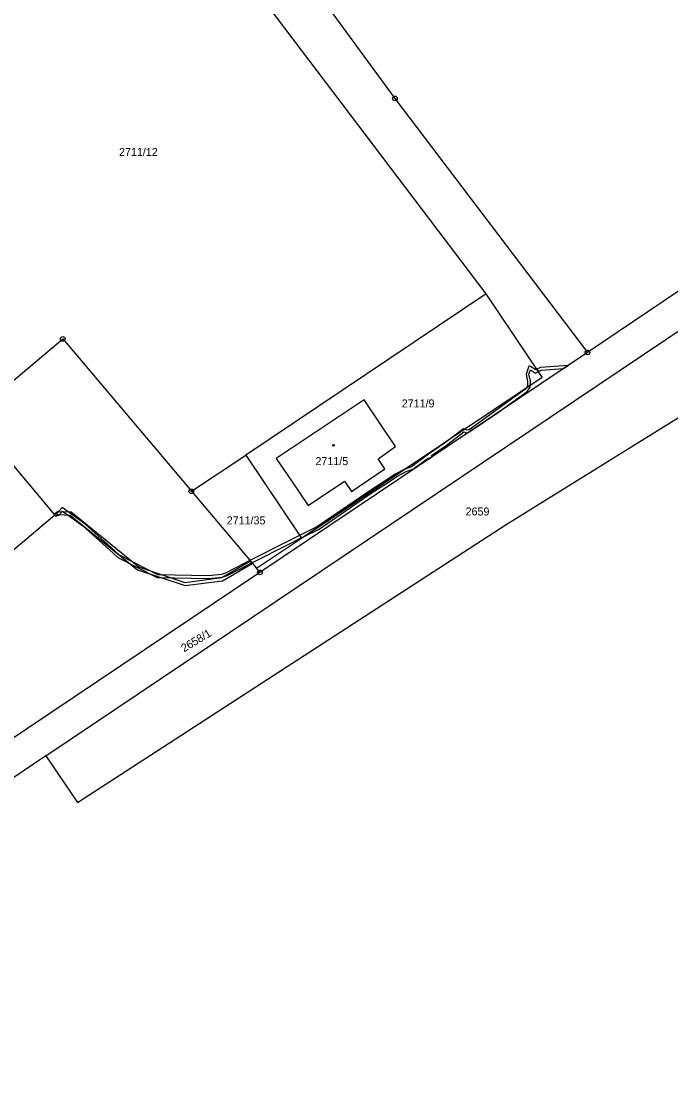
# Model space of a CAD drawing. Extents: x -562167 to -556918, y -1077891 to -1070763.
# Drawn here: x -561195.6 to -561057.6, y -1075746.5 to -1075522.2 of the extents above; entities that cross this region are included whole.
import ezdxf

# ---------------------------------------------------------------- set-up
doc = ezdxf.new("R2010")
doc.units = 0
for name, color, linetype in [('Hranice parcel', 7, 'Continuous'), ('Parcelní čísla', 7, 'Continuous'), ('Věcná břemena k části', 7, 'Continuous'), ('Značky bodu BP', 7, 'Continuous'), ('Značky budov', 7, 'Continuous')]:
    doc.layers.add(name, color=color, linetype=linetype)

msp = doc.modelspace()

# ---------------------------------------------------------------- linework, layer by layer
at = {"layer": 'Hranice parcel'}
for p, q in [((-561052.89, -1075577.55), (-561075.29, -1075592.6)), ((-561096.76, -1075580.15), (-561147.86, -1075614.39)), ((-561075.29, -1075592.6), (-561144.84, -1075639.34)), ((-561122.73, -1075602.7), (-561141.37, -1075615.12)), ((-561159.41, -1075622.1), (-561147.86, -1075614.39)), ((-561147.86, -1075614.39), (-561136.01, -1075632.09)), ((-561159.41, -1075622.1), (-561145.59, -1075638.46)), ((-561145.59, -1075638.46), (-561136.01, -1075632.09)), ((-561144.84, -1075639.34), (-561145.59, -1075638.46)), ((-561190.29, -1075678.29), (-561291.97, -1075746.53))]:
    msp.add_line(p, q, dxfattribs=at)
for points in [[(-561192.98, -1075442.18), (-561152.03, -1075491.45), (-561130.12, -1075519.56), (-561116.17, -1075538.61), (-561075.29, -1075592.6)], [(-561096.76, -1075580.15), (-561166.81, -1075487.64), (-561244.99, -1075544.16)], [(-561190.29, -1075678.29), (-561048.71, -1075583.16), (-561017.82, -1075561.43)], [(-561190.29, -1075678.29), (-561183.6, -1075688.25), (-561092.57, -1075629.13), (-561039.17, -1075596), (-561011.55, -1075569.85)], [(-561136.01, -1075632.09), (-561084.9, -1075597.84), (-561096.76, -1075580.15)], [(-561200.81, -1075601.59), (-561195.77, -1075597.33), (-561186.73, -1075589.72), (-561159.41, -1075622.1)], [(-561141.37, -1075615.12), (-561138.14, -1075619.9), (-561134.58, -1075625.14), (-561126.9, -1075619.93), (-561125.39, -1075622.11), (-561118.3, -1075617.3), (-561119.7, -1075615.23), (-561116.05, -1075612.57), (-561122.73, -1075602.7)], [(-561197.14, -1075616.68), (-561244.7, -1075656.87), (-561235.97, -1075667.26), (-561188.38, -1075627.09), (-561197.14, -1075616.68)], [(-561144.84, -1075639.34), (-561194.19, -1075672.48), (-561227.05, -1075694.53)]]:
    msp.add_lwpolyline(points, dxfattribs=at)
at = {"layer": 'Věcná břemena k části'}
for points in [[(-561087.99, -1075598.77), (-561088.02, -1075599.75), (-561088.27, -1075600.1), (-561087.41, -1075599.52), (-561087.39, -1075598.71), (-561087.7, -1075597.23), (-561087.38, -1075596.29), (-561086.3, -1075596.97), (-561085.69, -1075596.67), (-561086.02, -1075596.17), (-561086.26, -1075596.29), (-561087.18, -1075595.7), (-561087.5, -1075595.5), (-561087.78, -1075595.6), (-561087.9, -1075595.96), (-561088.32, -1075597.19)], [(-561085.28, -1075595.8), (-561086.02, -1075596.17), (-561085.69, -1075596.67), (-561085.12, -1075596.38), (-561080.41, -1075596.04), (-561079.4, -1075595.36)], [(-561088.55, -1075600.49), (-561100.43, -1075609.07), (-561100.9, -1075609.1), (-561101.41, -1075608.9), (-561103.95, -1075610.6), (-561105.63, -1075611.9), (-561109.07, -1075614.23), (-561112.68, -1075616.89), (-561113.99, -1075617.37), (-561114.23, -1075617.5), (-561135.33, -1075631.63), (-561132.28, -1075630.12), (-561120.97, -1075622.35), (-561117.74, -1075620.33), (-561115.79, -1075618.95), (-561113.75, -1075617.93), (-561112.4, -1075617.43), (-561109.06, -1075614.97), (-561108.9, -1075615.19), (-561108.24, -1075614.74), (-561108.4, -1075614.51), (-561105.27, -1075612.38), (-561101.53, -1075609.5), (-561101, -1075609.7), (-561100.72, -1075609.69), (-561094.14, -1075605.27), (-561088.11, -1075600.91), (-561087.42, -1075599.95), (-561087.41, -1075599.52), (-561088.27, -1075600.1)], [(-561103.95, -1075610.6), (-561101.41, -1075608.9), (-561101.63, -1075608.82)], [(-561136.07, -1075632), (-561135.33, -1075631.63), (-561114.23, -1075617.5), (-561116.09, -1075618.43), (-561118.08, -1075619.83), (-561121.29, -1075621.85), (-561132.58, -1075629.6), (-561136.41, -1075631.5), (-561139.11, -1075632.84), (-561146.96, -1075636.84), (-561146.56, -1075637.31), (-561138.85, -1075633.38)], [(-561176.87, -1075634.47), (-561175.02, -1075636.14), (-561166.7, -1075640.45), (-561155.71, -1075640.65), (-561152.9, -1075640.38), (-561151.93, -1075640.05), (-561146.56, -1075637.31), (-561146.96, -1075636.84), (-561152.17, -1075639.49), (-561153.02, -1075639.78), (-561155.73, -1075640.05), (-561166.54, -1075639.85), (-561174.68, -1075635.64), (-561176.47, -1075634.03), (-561182.05, -1075628.98), (-561186.85, -1075625.54), (-561188.04, -1075626.87), (-561187.6, -1075627.27), (-561186.77, -1075626.34), (-561182.43, -1075629.44)], [(-561170.86, -1075638.77), (-561160.75, -1075642.13), (-561152.81, -1075641.1), (-561146.48, -1075637.41), (-561146.87, -1075636.94), (-561153.01, -1075640.52), (-561160.69, -1075641.52), (-561170.56, -1075638.23), (-561184.93, -1075626.57), (-561187.87, -1075626.46), (-561188.48, -1075626.97), (-561188.38, -1075627.09), (-561188.09, -1075627.43), (-561187.66, -1075627.06), (-561185.16, -1075627.17)]]:
    msp.add_lwpolyline(points, close=True, dxfattribs=at)
at = {"layer": 'Značky bodu BP'}
for centre, radius in [((-561116.17, -1075538.61), 0.5), ((-561116.17, -1075538.61), 0.0303), ((-561186.73, -1075589.72), 0.5), ((-561186.73, -1075589.72), 0.0303), ((-561075.29, -1075592.6), 0.5), ((-561075.29, -1075592.6), 0.0303), ((-561159.41, -1075622.1), 0.5), ((-561159.41, -1075622.1), 0.0303), ((-561144.84, -1075639.34), 0.5), ((-561144.84, -1075639.34), 0.0303)]:
    msp.add_circle(centre, radius, dxfattribs=at)
at = {"layer": 'Značky budov'}
msp.add_circle((-561129.22, -1075612.33), 0.175, dxfattribs=at)

# ---------------------------------------------------------------- texts
at = {"layer": 'Parcelní čísla'}
for s, p in [('2711/12', (-561174.77, -1075550.85)), ('2711/9', (-561114.72, -1075604.28)), ('2711/5', (-561133.05, -1075616.54)), ('2659', (-561101.16, -1075627.24)), ('2711/35', (-561151.89, -1075629.13))]:
    msp.add_text(s, height=1.7, dxfattribs=at).set_placement(p)
msp.add_text('2658/1', height=1.7, rotation=31, dxfattribs=at).set_placement((-561160.95, -1075656.32))

doc.saveas('drawing.dxf')
